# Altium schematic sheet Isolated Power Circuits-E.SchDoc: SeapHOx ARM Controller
size Letter; DocumentNumber: 1; Revision: E; SheetNumber: 2; SheetTotal: 7; PageSetup: Record=PageOptions¦CenterHorizontal=True¦CenterVertical=True¦PrintScale=0.94¦XCorrection=1.00¦YCorrection=1.00¦PrintKind=0¦BorderSize=5000000¦LeftOffset=0¦BottomOffset=0¦Orientation=2¦PaperLength=1000¦PaperWidth=1000¦Scale=100¦PaperSource=7¦PrintQuality=-4¦MediaType=1¦DitherType=10¦PaperKind=Letter¦PrintScaleMode=1
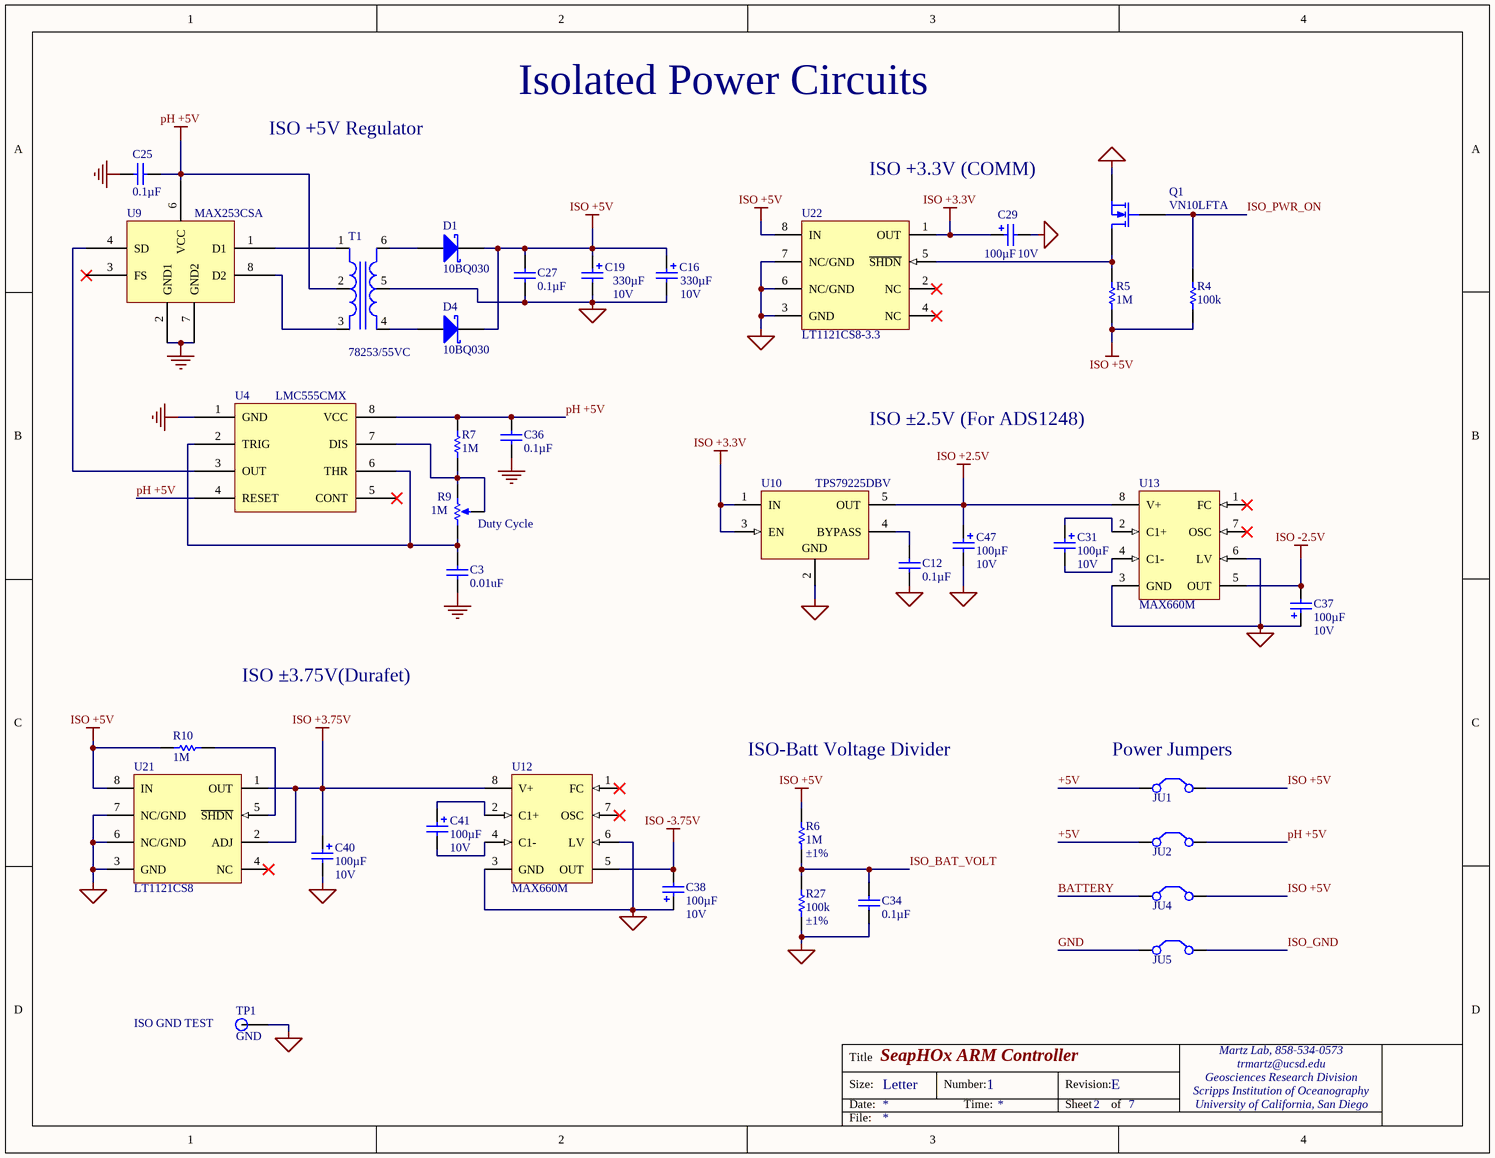
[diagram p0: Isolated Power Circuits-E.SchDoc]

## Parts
C3  0.01uF  [CAPC0603(1608)100_M]
C12  Capacitance: 0.1µF  [CAPC0603(1608)100_M]  (hidden comment: 0.1uF/50V)
C16  Voltage - Rated: 10V  Capacitance: 330µF  [CAPMP7343X29N]  (hidden comment: TR3D337M010C0100)
C19  Voltage - Rated: 10V  Capacitance: 330µF  [CAPMP7343X29N]  (hidden comment: TR3D337M010C0100)
C25  Capacitance: 0.1µF  [CAPC0603(1608)100_M]  (hidden comment: 0.1uF/50V)
C27  Capacitance: 0.1µF  [CAPC0603(1608)100_M]  (hidden comment: 0.1uF/50V)
C29  Capacitance: 100µF  Voltage - Rated: 10V  [CAPMP7343X29N]  (hidden comment: T495D107K010ATE100)
C31  Capacitance: 100µF  Voltage - Rated: 10V  [CAPMP7343X29N]  (hidden comment: T495D107K010ATE100)
C34  Capacitance: 0.1µF  [CAPC0603(1608)100_M]  (hidden comment: 0.1uF/50V)
C36  Capacitance: 0.1µF  [CAPC0603(1608)100_M]  (hidden comment: 0.1uF/50V)
C37  Capacitance: 100µF  Voltage - Rated: 10V  [CAPMP7343X29N]  (hidden comment: T495D107K010ATE100)
C38  Capacitance: 100µF  Voltage - Rated: 10V  [CAPMP7343X29N]  (hidden comment: T495D107K010ATE100)
C40  Capacitance: 100µF  Voltage - Rated: 10V  [CAPMP7343X29N]  (hidden comment: T495D107K010ATE100)
C41  Capacitance: 100µF  Voltage - Rated: 10V  [CAPMP7343X29N]  (hidden comment: T495D107K010ATE100)
C47  Capacitance: 100µF  Voltage - Rated: 10V  [CAPMP7343X29N]  (hidden comment: T495D107K010ATE100)
D1  10BQ030  [DO214AA]
D4  10BQ030  [DO214AA]
JU1  68001-202HLF  [Jump-2 100mil]  (value not drawn)
JU2  68001-202HLF  [Jump-2 100mil]  (value not drawn)
JU4  68001-202HLF  [Jump-2 100mil]  (value not drawn)
JU5  68001-202HLF  [Jump-2 100mil]  (value not drawn)
Q1  VN10LFTA  [SOT23-3]
R4  Resistance (Ohms): 100k  [RESC0805(2012)_N]  (hidden comment: ERJ-6GEYJ104V)
R5  Resistance (Ohms): 1M  [RESC0805(2012)_N]  (hidden comment: ERJ-6GEYJ105V)
R6  Resistance (Ohms): 1M  Tolerance: ±1%  [RESC0805(2012)_N]  (hidden comment: ERJ-6ENF1004V)
R7  Resistance (Ohms): 1M  [RESC0805(2012)_N]  (hidden comment: ERJ-6GEYJ105V)
R9  Resistance (Ohms): 1M  [3269W]  (hidden comment: 3269W-1-105GLF)
R10  Resistance (Ohms): 1M  [RESC0805(2012)_N]  (hidden comment: ERJ-6GEYJ105V)
R27  Resistance (Ohms): 100k  Tolerance: ±1%  [RESC0805(2012)_N]  (hidden comment: ERJ-6ENF1003V)
T1  78253/55VC  [DIP6]
TP1  GND  [TEST-POINT-0.063]
U4  LMC555CMX  [MS-012-AA]
U9  MAX253CSA  [SOIC8]
U10  TPS79225DBV  [TI-DBV5]
U12  MAX660M  [SOIC8]
U13  MAX660M  [SOIC8]
U21  LT1121CS8  [SOIC8]
U22  LT1121CS8-3.3  [SOIC8]

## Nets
GND: C3.2 C25.2 C36.1 JU5.1(C1) U4.1(GND) U9.2(GND1) U9.7(GND2)
ISO +2.5V: C47.1 U10.5(OUT) U13.8(V+)
ISO +3.3V: C29.1 U10.1(IN) U10.3(EN) U22.1(OUT)
ISO +3.75V: C40.1 U12.8(V+) U21.1(OUT) U21.2(ADJ)
ISO +5V: C16.1 C19.1 C27.2 D1.2(K) D4.2(K) JU1.2(C2) JU4.2(C2) R4.1 R5.1 R6.2 R10.2 U21.8(IN) U22.8(IN)
ISO -2.5V: C37.2 U13.5(OUT)
ISO -3.75V: C38.2 U12.5(OUT)
ISO_GND: C12.1 C16.2 C19.2 C27.1 C29.2 C34.1 C37.1 C38.1 C40.2 C47.2 JU5.2(C2) Q1.2(S) R27.1 T1.5(SCT) TP1.1(TP) U10.2(GND) U12.3(GND) U12.6(LV) U13.3(GND) U13.6(LV) U21.3(GND) U21.6(NC/GND) U21.7(NC/GND) U22.3(GND) U22.6(NC/GND) U22.7(NC/GND)
pH +5V: C25.1 C36.2 JU2.2(C2) R7.2 T1.2(PCT) U4.4(RESET) U4.8(VCC) U9.6(VCC)
+5V: JU1.1(C1) JU2.1(C1)
BATTERY: JU4.1(C1)
ISO_BAT_VOLT: C34.2 R6.1 R27.2
ISO_PWR_ON: Q1.1(G) R4.2
NetC3_1: C3.1 R9.3(CW) U4.2(TRIG) U4.6(THR)
NetC12_2: C12.2 U10.4(BYPASS)
NetC31_1: C31.1 U13.2(C1+)
NetC31_2: C31.2 U13.4(C1-)
NetC41_1: C41.1 U12.2(C1+)
NetC41_2: C41.2 U12.4(C1-)
NetD1_1: D1.1(A) T1.6(S1)
NetD4_1: D4.1(A) T1.4(S2)
NetQ1_3: Q1.3(D) R5.2 U22.5(~{SHDN})
NetR7_1: R7.1 R9.1(CCW) R9.2(W) U4.7(DIS)
NetR10_1: R10.1 U21.5(~{SHDN})
NetT1_1: T1.1(P1) U9.1(D1)
NetT1_3: T1.3(P2) U9.8(D2)
NetU4_3: U4.3(OUT) U9.4(SD)

Not connected (* = marked no-connect by the designer): U4 5(CONT)*; U9 3(FS)*; U12 1(FC)* 7(OSC)*; U13 1(FC)* 7(OSC)*; U21 4(NC)*; U22 2(NC)* 4(NC)*

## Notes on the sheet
- Isolated Power Circuits
- ISO +5V Regulator
- ISO +3.3V (COMM)
- ISO ±2.5V (For ADS1248)
- (near R9) Duty Cycle
- ISO ±3.75V(Durafet)
- ISO-Batt Voltage Divider
- (near JU1) Power Jumpers
- (near TP1) ISO GND TEST

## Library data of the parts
C3 = C1608X7R1H103K080AA: CAP CER 10000PF 50V 10% X7R 0603; Manufacturer: TDK Corporation
C12 C25 C27 C34 C36 = C0603C104K5RACTU: CAP CER 0.1UF 50V 10% X7R 0603; Manufacturer: Kemet
C16 C19 = TR3D337M010C0100: CAP TANT 330UF 10V 20% 2917; Manufacturer: Vishay Sprague; Manufacturer Size Code: D; ESR (Equivalent Series Resistance): 100 mOhm; Type: Molded
C29 C31 C37 C38 C40 C41 C47 = T495D107K010ATE100: CAP TANT 100UF 10V 10% 2917; Manufacturer: Kemet; Manufacturer Size Code: D; ESR (Equivalent Series Resistance): 100 mOhm; Type: Molded; Lifetime @ Temp.: 2000 Hrs @ 85°C
D1 D4 = VS-10BQ030TRPBF: DIODE SCHOTTKY 30V 1A DO214AA; Manufacturer: Vishay Semiconductor Diodes Division; Voltage - Forward (Vf) (Max) @ If: 420mV @ 1A; Speed: Fast Recovery =< 500ns, > 200mA (Io); Current - Reverse Leakage @ Vr: 500µA @ 30V; Thermal Resistance: 25°C/W Jl
JU1 JU2 JU4 JU5 = 68001-202HLF: BERGSTIK II .100" SR STRAIGHT; Manufacturer: FCI; Connector Type: Header, Unshrouded; Number of Positions: 2; Number of Positions Loaded: All; Pitch: 0.100" (2.54mm)
Q1 = VN10LFTA: MOSFET N-CH 60V 150MA SOT23-3; Manufacturer: Diodes Inc; FET Type: MOSFET N-Channel, Metal Oxide; FET Feature: Standard; Current - Continuous Drain (Id) @ 25° C: 150mA (Ta); Rds On (Max) @ Id, Vgs: 5 Ohm @ 500mA, 10V; Vgs(th) (Max) @ Id: 2.5V @ 1mA; Input Capacitance (Ciss) @ Vds: 60pF @ 25V; Power - Max: 330mW
R4 = ERJ-6GEYJ104V: RES 100K OHM 1/8W 5% 0805 SMD; Manufacturer: Panasonic Electronic Components; Power (Watts): 0.125W, 1/8W; Temperature Coefficient: ±200ppm/°C
R5 R7 R10 = ERJ-6GEYJ105V: RES 1M OHM 1/8W 5% 0805 SMD; Manufacturer: Panasonic Electronic Components; Power (Watts): 0.125W, 1/8W; Temperature Coefficient: ±200ppm/°C
R6 = ERJ-6ENF1004V: RES 1M OHM 1/8W 1% 0805 SMD; Manufacturer: Panasonic Electronic Components; Power (Watts): 0.125W, 1/8W; Temperature Coefficient: ±100ppm/°C
R9 = 3269W-1-105GLF: TRIMMER 1M OHM 0.25W SMD; Manufacturer: Bourns Inc.; Power (Watts): 0.25W, 1/4W; Temperature Coefficient: ±100ppm/°C; Tolerance: ±10%; Number of Turns: 12; Adjustment Type: Top Adjustment; Resistive Material: Cermet
R27 = ERJ-6ENF1003V: RES 100K OHM 1/8W 1% 0805 SMD; Manufacturer: Panasonic Electronic Components; Power (Watts): 0.125W, 1/8W; Temperature Coefficient: ±100ppm/°C
T1 = 78253/55VC: XFRMR 5V IN/OUT MAX 253 DIP; Manufacturer: Murata Power Solutions Inc; Inductance: 240µH; For Use With/Related Products: MAX253
TP1 = 5006: TEST POINT PC COMPACT .063"D BLK; Manufacturer: Keystone Electronics
U4 = LMC555CMX: IC OSC MONO TIMING 3MHZ 8-SOIC; Manufacturer: Texas Instruments; Voltage - Supply: 1.5 V ~ 15 V; Current - Supply: 150µA
U9 = MAX253CSA: Gate Drivers Transformer Driver for Iso RS-485 Int; Manufacturer: Maxim Integrated; Manufacturer Part Number: MAX253CSA+; Output Current: 1 A; Supply Current: 0.45 mA; Maximum Power Dissipation: 471 mW; Number of Drivers: 1; Operating Supply Voltage: 3.3 V, 5 V; Supply Voltage - Max: 6 V; Supply Voltage - Min: 2.5 V
U10 = TPS79225DBVT: IC REG LDO 2.5V 0.1A SOT23-5; Manufacturer: Texas Instruments; Number of Regulators: 1; Regulator Topology: Positive Fixed; Voltage - Input: 2.7 V ~ 5.5 V; Current - Output: 100mA (Max); Current - Limit (Min): 285mA
U12 U13 = MAX660M: IC REG MULTI CONFIG ADJ 8-SOIC; Manufacturer: Texas Instruments; Manufacturer Part Number: MAX660MX/NOPB; Output Type: Adjustable; Number of Outputs: 1; Voltage - Input: 1.5 V ~ 5.5 V; Frequency - Switching: 10kHz, 80kHz; Current - Output: 100mA; Synchronous Rectifier: No
U21 = LT1121CS8: IC REG LDO ADJ 0.15A 8SOIC; Manufacturer: Linear Technology; Manufacturer Part Number: LT1121CS8#PBF; Number of Regulators: 1; Regulator Topology: Positive Adjustable; Voltage - Input: 4.17 V ~ 30 V; Voltage - Output: 3.75 V ~ 30 V; Voltage - Dropout (Typical): 0.42V @ 150mA; Current - Output: 150mA
U22 = LT1121CS8-3.3: IC REG LDO 3.3V 0.15A 8SOIC; Manufacturer: Linear Technology; Manufacturer Part Number: LT1121CS8-3.3#PBF; Number of Regulators: 1; Regulator Topology: Positive Fixed; Voltage - Input: 4.17 V ~ 30 V; Voltage - Dropout (Typical): 0.42V @ 150mA; Current - Output: 150mA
